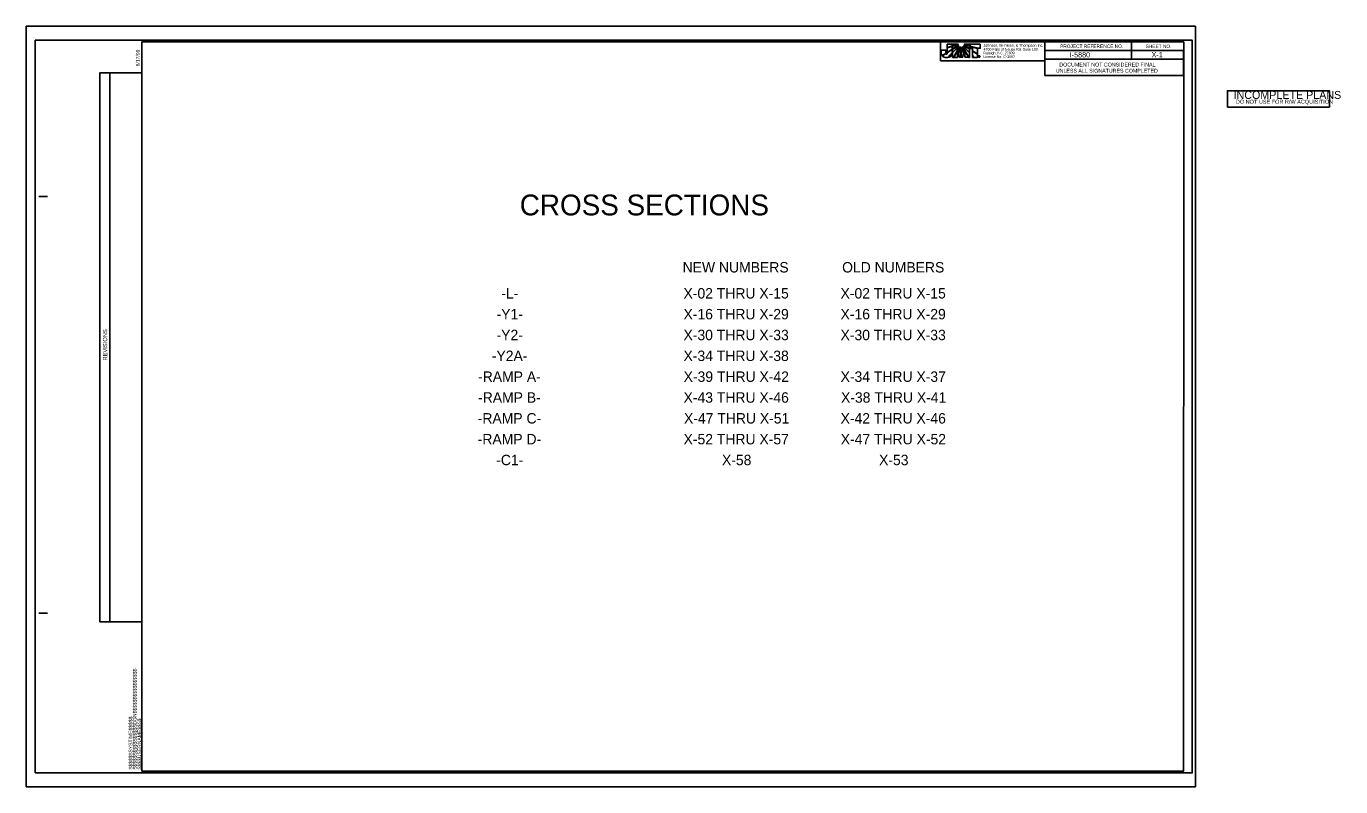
# Model space of a CAD drawing. Extents: x 2862872 to 2864765, y 971793 to 972888.
import ezdxf

# ---------------------------------------------------------------- set-up
doc = ezdxf.new("R2010")
doc.units = 0
for name, color, linetype in [('Prop Dimension Text', 7, 'Continuous'), ('Scratch_Level_0', 7, 'Continuous'), ('Sheet Block Revision CELL', 7, 'Continuous'), ('Sheet Cutting Line CELL', 7, 'Continuous'), ('Sheet Data Field CELL', 7, 'Continuous'), ('Sheet Plan CELL', 7, 'Continuous'), ('Sheet Plot Border Inside CELL', 7, 'Continuous'), ('Sheet Plot Border Outside CELL', 7, 'Continuous'), ('Sheet Sticker Exception Certification CELL', 7, 'Continuous'), ('Sheet Sticker Incomplete CELL', 7, 'Continuous'), ('Sheet XS Number', 7, 'Continuous')]:
    doc.layers.add(name, color=color, linetype=linetype)

msp = doc.modelspace()

# ---------------------------------------------------------------- linework, layer by layer
at = {"layer": 'Prop Dimension Text'}
for p, q in [((2864205.2, 972862.5), (2864198.2, 972862.5)), ((2864198.2, 972862.5), (2864198.2, 972857.9)), ((2864198.2, 972857.9), (2864205.2, 972859.8)), ((2864205.2, 972859.3), (2864198.2, 972857.3)), ((2864198.2, 972857.3), (2864198.2, 972850.8)), ((2864198.2, 972850.8), (2864205.2, 972855.2)), ((2864205.2, 972859.8), (2864205.2, 972862.5)), ((2864205.2, 972855.2), (2864205.2, 972859.3)), ((2864213.8, 972862.6), (2864205.9, 972862.6)), ((2864205.9, 972862.6), (2864205.9, 972860.1)), ((2864205.9, 972860.1), (2864211.8, 972861.7)), ((2864211.8, 972861.1), (2864205.9, 972859.5)), ((2864205.9, 972859.5), (2864205.9, 972855.7)), ((2864205.9, 972855.7), (2864211.2, 972859.1)), ((2864212, 972859), (2864205.9, 972855.1)), ((2864205.9, 972850.7), (2864213.3, 972858.4)), ((2864213.6, 972858), (2864205.9, 972850)), ((2864205.9, 972855.1), (2864205.9, 972850.7)), ((2864205.9, 972850), (2864205.9, 972843.6)), ((2864207.1, 972843.6), (2864212.8, 972854)), ((2864212.8, 972853), (2864207.6, 972843.6)), ((2864211.2, 972859.1), (2864214.1, 972861.4)), ((2864211.8, 972861.7), (2864213.8, 972862.6)), ((2864214.1, 972861.4), (2864211.8, 972861.1)), ((2864214.7, 972860.3), (2864212, 972859)), ((2864212.8, 972854), (2864212.8, 972855.8)), ((2864212.8, 972855.8), (2864213.1, 972854.6)), ((2864212.9, 972843.6), (2864212.8, 972853)), ((2864213.1, 972854.6), (2864214.6, 972857.2)), ((2864213.3, 972858.4), (2864214.7, 972860.3)), ((2864215.1, 972857.1), (2864213.3, 972853.9)), ((2864213.3, 972853.9), (2864214.5, 972849.7)), ((2864215.5, 972859.5), (2864213.6, 972858)), ((2864214.5, 972849.7), (2864216.3, 972856.7)), ((2864214.6, 972857.2), (2864215.5, 972859.5)), ((2864216.7, 972856.3), (2864214.7, 972848.7)), ((2864216.5, 972858.9), (2864215.1, 972857.1)), ((2864216.3, 972856.7), (2864216.5, 972858.9)), ((2864217.6, 972858.5), (2864216.7, 972856.3)), ((2864217.9, 972853), (2864217.6, 972858.5)), ((2864218, 972843.7), (2864217.9, 972853)), ((2864218.8, 972858.5), (2864218.4, 972853)), ((2864218.4, 972853), (2864218.5, 972843.7)), ((2864219.7, 972856.3), (2864218.8, 972858.5)), ((2864221.7, 972848.6), (2864219.7, 972856.3)), ((2864219.9, 972858.9), (2864220.2, 972856.6)), ((2864221.3, 972857.1), (2864219.9, 972858.9)), ((2864220.2, 972856.6), (2864222, 972849.5)), ((2864220.9, 972859.5), (2864221.8, 972857.2)), ((2864222.8, 972858.1), (2864220.9, 972859.5)), ((2864223.1, 972853.8), (2864221.3, 972857.1)), ((2864221.7, 972860.3), (2864223.1, 972858.4)), ((2864224.4, 972859), (2864221.7, 972860.3)), ((2864221.8, 972857.2), (2864223.3, 972854.5)), ((2864222, 972849.5), (2864223.1, 972853.8)), ((2864222.3, 972861.4), (2864225.3, 972859)), ((2864224.5, 972861.1), (2864222.3, 972861.4)), ((2864230.5, 972862.6), (2864222.7, 972862.6)), ((2864222.7, 972862.6), (2864224.7, 972861.7)), ((2864230.5, 972849.9), (2864222.8, 972858.1)), ((2864223.1, 972858.4), (2864230.5, 972850.7)), ((2864223.3, 972854.5), (2864223.6, 972855.8)), ((2864223.6, 972855.8), (2864223.6, 972853.8)), ((2864223.6, 972853.8), (2864229.3, 972843.6)), ((2864228.7, 972843.7), (2864223.6, 972852.8)), ((2864223.6, 972852.8), (2864223.6, 972843.7)), ((2864230.5, 972855.2), (2864224.4, 972859)), ((2864230.5, 972859.5), (2864224.5, 972861.1)), ((2864224.7, 972861.7), (2864230.5, 972860)), ((2864225.3, 972859), (2864230.5, 972855.8)), ((2864230.5, 972860), (2864230.5, 972862.6)), ((2864230.5, 972855.8), (2864230.5, 972859.5)), ((2864230.5, 972850.7), (2864230.5, 972855.2)), ((2864230.5, 972843.6), (2864230.5, 972849.9)), ((2864245.8, 972862.6), (2864231.1, 972862.6)), ((2864231.1, 972862.6), (2864231.1, 972859.9)), ((2864231.1, 972859.9), (2864231.1, 972859.8)), ((2864231.1, 972859.8), (2864242.7, 972856.6)), ((2864231.1, 972859.4), (2864231.1, 972859.3)), ((2864241.9, 972856.3), (2864231.1, 972859.4)), ((2864231.1, 972859.3), (2864231.1, 972856.5)), ((2864231.1, 972856.5), (2864234.7, 972856.5)), ((2864234.7, 972856.5), (2864234.7, 972853.1)), ((2864234.7, 972853.1), (2864241.9, 972848.5)), ((2864234.7, 972852.6), (2864234.7, 972846.3)), ((2864241.9, 972848), (2864234.7, 972852.6)), ((2864241.9, 972848.5), (2864241.9, 972856.3)), ((2864242.7, 972856.6), (2864245.8, 972856.6)), ((2864245.8, 972856.6), (2864245.8, 972862.6)), ((2864205.9, 972843.6), (2864207.1, 972843.6)), ((2864207.6, 972843.6), (2864212.9, 972843.6)), ((2864214.7, 972848.7), (2864216, 972843.7)), ((2864216, 972843.7), (2864218, 972843.7)), ((2864218.5, 972843.7), (2864220.4, 972843.7)), ((2864220.4, 972843.7), (2864221.7, 972848.6)), ((2864223.6, 972843.7), (2864228.7, 972843.7)), ((2864229.3, 972843.6), (2864230.5, 972843.6)), ((2864234.7, 972846.3), (2864237.2, 972843.6)), ((2864236.5, 972843.6), (2864234.7, 972845.6)), ((2864234.7, 972845.6), (2864234.7, 972843.6)), ((2864234.7, 972843.6), (2864236.5, 972843.6)), ((2864237.2, 972843.6), (2864242, 972843.6)), ((2864242, 972843.6), (2864241.9, 972848)), ((2864243.8, 972844.3), (2864243.8, 972845.4)), ((2864243.8, 972845.4), (2864244.2, 972845.4)), ((2864244, 972844.3), (2864243.8, 972844.3)), ((2864244.2, 972845.2), (2864244, 972845.2)), ((2864244, 972845.2), (2864244, 972844.9)), ((2864244, 972844.9), (2864244.2, 972844.9)), ((2864244.2, 972844.7), (2864244, 972844.7)), ((2864244, 972844.7), (2864244, 972844.3)), ((2864244.2, 972846), (2864244.2, 972845.8)), ((2864244.2, 972845.8), (2864244.2, 972846)), ((2864244.2, 972845.4), (2864244.2, 972845.2)), ((2864244.2, 972845.2), (2864244.2, 972845.4)), ((2864244.2, 972845.4), (2864244.3, 972845.4)), ((2864244.3, 972845.2), (2864244.2, 972845.2)), ((2864244.2, 972844.9), (2864244.2, 972844.7)), ((2864244.2, 972844.7), (2864244.2, 972844.9)), ((2864244.2, 972844.9), (2864244.2, 972844.9)), ((2864244.2, 972844.7), (2864244.2, 972844.7)), ((2864244.2, 972843.9), (2864244.2, 972843.7)), ((2864244.2, 972843.7), (2864244.2, 972843.9)), ((2864244.2, 972843.9), (2864244.2, 972843.9)), ((2864244.2, 972843.7), (2864244.2, 972843.7))]:
    msp.add_line(p, q, dxfattribs=at)
msp.add_lwpolyline([(2864188.7, 972838.8), (2864338.6, 972838.8), (2864338.6, 972865.8), (2864188.7, 972865.8)], close=True, dxfattribs=at)
for points in [[(2864198.2, 972857.9), (2864205.2, 972859.8), (2864205.2, 972862.5), (2864198.2, 972862.5), (2864198.2, 972857.9)], [(2864198.2, 972850.8), (2864205.2, 972855.2), (2864205.2, 972859.3), (2864198.2, 972857.3), (2864198.2, 972850.8)], [(2864211.8, 972861.7), (2864213.8, 972862.6), (2864205.9, 972862.6), (2864205.9, 972860.1), (2864211.8, 972861.7)], [(2864205.9, 972859.5), (2864205.9, 972855.7), (2864211.2, 972859.1), (2864214.1, 972861.4), (2864211.8, 972861.1), (2864205.9, 972859.5)], [(2864205.9, 972855.1), (2864205.9, 972850.7), (2864213.3, 972858.4), (2864214.7, 972860.3), (2864212, 972859), (2864205.9, 972855.1)], [(2864215.5, 972859.5), (2864213.6, 972858), (2864205.9, 972850), (2864205.9, 972843.6), (2864207.1, 972843.6), (2864212.8, 972854), (2864212.8, 972855.8), (2864213.1, 972854.6), (2864214.6, 972857.2), (2864215.5, 972859.5)], [(2864207.6, 972843.6), (2864212.9, 972843.6), (2864212.8, 972853), (2864207.6, 972843.6)], [(2864216.5, 972858.9), (2864215.1, 972857.1), (2864213.3, 972853.9), (2864214.5, 972849.7), (2864216.3, 972856.7), (2864216.5, 972858.9)], [(2864216.7, 972856.3), (2864214.7, 972848.7), (2864216, 972843.7), (2864218, 972843.7), (2864217.9, 972853), (2864217.6, 972858.5), (2864216.7, 972856.3)], [(2864218.8, 972858.5), (2864218.4, 972853), (2864218.5, 972843.7), (2864220.4, 972843.7), (2864221.7, 972848.6), (2864219.7, 972856.3), (2864218.8, 972858.5)], [(2864219.9, 972858.9), (2864220.2, 972856.6), (2864222, 972849.5), (2864223.1, 972853.8), (2864221.3, 972857.1), (2864219.9, 972858.9)], [(2864220.9, 972859.5), (2864221.8, 972857.2), (2864223.3, 972854.5), (2864223.6, 972855.8), (2864223.6, 972853.8), (2864229.3, 972843.6), (2864230.5, 972843.6), (2864230.5, 972849.9), (2864222.8, 972858.1), (2864220.9, 972859.5)], [(2864221.7, 972860.3), (2864223.1, 972858.4), (2864230.5, 972850.7), (2864230.5, 972855.2), (2864224.4, 972859), (2864221.7, 972860.3)], [(2864222.3, 972861.4), (2864225.3, 972859), (2864230.5, 972855.8), (2864230.5, 972859.5), (2864224.5, 972861.1), (2864222.3, 972861.4)], [(2864224.7, 972861.7), (2864230.5, 972860), (2864230.5, 972862.6), (2864222.7, 972862.6), (2864224.7, 972861.7)], [(2864223.6, 972843.7), (2864228.7, 972843.7), (2864223.6, 972852.8), (2864223.6, 972843.7)], [(2864245.8, 972862.6), (2864231.1, 972862.6), (2864231.1, 972859.9), (2864231.1, 972859.8), (2864242.7, 972856.6), (2864245.8, 972856.6), (2864245.8, 972862.6)], [(2864231.1, 972859.4), (2864231.1, 972859.3), (2864231.1, 972856.5), (2864234.7, 972856.5), (2864234.7, 972853.1), (2864241.9, 972848.5), (2864241.9, 972856.3), (2864231.1, 972859.4)], [(2864234.7, 972852.6), (2864234.7, 972846.3), (2864237.2, 972843.6), (2864242, 972843.6), (2864241.9, 972848), (2864234.7, 972852.6), (2864234.7, 972852.6)], [(2864234.7, 972843.6), (2864234.7, 972843.6), (2864236.5, 972843.6), (2864234.7, 972845.6), (2864234.7, 972843.6)], [(2864244.7, 972844.6), (2864244.7, 972844.5), (2864244.7, 972844.5), (2864244.7, 972844.4), (2864244.7, 972844.3), (2864244.5, 972844.3)]]:
    msp.add_lwpolyline(points, dxfattribs=at)
for points, degree in [([(2864196.2, 972853.8), (2864196.2, 972853.8), (2864189.7, 972853.8), (2864189.7, 972853.8), (2864189.7, 972853.8), (2864189.7, 972849.7), (2864189.7, 972849.7), (2864189.7, 972849.7), (2864189.7, 972849.3), (2864189.7, 972849.3), (2864189.7, 972848), (2864190.1, 972847), (2864190.8, 972846.2), (2864190.8, 972846.2), (2864196.2, 972849.4), (2864196.2, 972849.5), (2864196.2, 972849.5), (2864196.2, 972853.8), (2864196.2, 972853.8)], 3), ([(2864197.2, 972848), (2864196.8, 972848), (2864196.4, 972848.2), (2864196.2, 972849), (2864196.2, 972849), (2864191.2, 972845.8), (2864191.2, 972845.8), (2864192.8, 972844.2), (2864195.2, 972843.2), (2864197.3, 972843.2), (2864197.9, 972843.2), (2864198.3, 972843.3), (2864198.9, 972843.4), (2864198.9, 972843.4), (2864205.2, 972849.9), (2864205.2, 972849.9), (2864205.2, 972849.9), (2864205.2, 972854.7), (2864205.2, 972854.7), (2864205.2, 972854.7), (2864198.2, 972850.2), (2864198.2, 972850.2), (2864198.2, 972848.4), (2864197.7, 972848), (2864197.2, 972848)], 3), ([(2864197.2, 972848), (2864196.8, 972848), (2864196.4, 972848.2), (2864196.2, 972849), (2864196.2, 972849), (2864191.2, 972845.8), (2864191.2, 972845.8), (2864192.8, 972844.2), (2864195.2, 972843.2), (2864197.3, 972843.2), (2864197.9, 972843.2), (2864198.3, 972843.3), (2864198.9, 972843.4), (2864198.9, 972843.4), (2864205.2, 972849.9), (2864205.2, 972849.9), (2864205.2, 972849.9), (2864205.2, 972854.7), (2864205.2, 972854.7), (2864205.2, 972854.7), (2864198.2, 972850.2), (2864198.2, 972850.2), (2864198.2, 972848.4), (2864197.7, 972848), (2864197.2, 972848)], 3), ([(2864205.2, 972849.2), (2864205.2, 972849.2), (2864199.7, 972843.6), (2864199.7, 972843.6), (2864202.4, 972844.2), (2864205.1, 972846), (2864205.2, 972849.2)], 3), ([(2864244.2, 972843.7), (2864243.9, 972843.7), (2864243.6, 972843.8), (2864243.4, 972844), (2864243.2, 972844.2), (2864243, 972844.5), (2864243, 972844.8), (2864243, 972845.2), (2864243.2, 972845.5), (2864243.4, 972845.7), (2864243.6, 972845.9), (2864243.9, 972846), (2864244.2, 972846)], 3), ([(2864244.2, 972845.8), (2864244, 972845.8), (2864243.7, 972845.7), (2864243.6, 972845.5), (2864243.4, 972845.3), (2864243.3, 972845.1), (2864243.3, 972844.8), (2864243.3, 972844.6), (2864243.4, 972844.4), (2864243.6, 972844.2), (2864243.7, 972844), (2864244, 972843.9), (2864244.2, 972843.9)], 3), ([(2864244.2, 972846), (2864244.6, 972846), (2864244.8, 972845.9), (2864245.1, 972845.7), (2864245.3, 972845.5), (2864245.4, 972845.2), (2864245.4, 972844.8)], 3), ([(2864244.2, 972843.9), (2864244.5, 972843.9), (2864244.7, 972844), (2864244.9, 972844.2), (2864245.1, 972844.4), (2864245.2, 972844.6), (2864245.2, 972844.8), (2864245.2, 972845.1), (2864245.1, 972845.3), (2864244.9, 972845.5), (2864244.7, 972845.7), (2864244.5, 972845.8), (2864244.2, 972845.8)], 3), ([(2864244.2, 972844.9), (2864244.4, 972844.9), (2864244.5, 972845), (2864244.5, 972845.1), (2864244.5, 972845.1), (2864244.4, 972845.2), (2864244.3, 972845.2)], 3), ([(2864245.4, 972844.8), (2864245.4, 972844.5), (2864245.3, 972844.2), (2864245.1, 972844), (2864244.9, 972843.8), (2864244.6, 972843.7), (2864244.2, 972843.7)], 3), ([(2864244.4, 972844.7), (2864244.4, 972844.7), (2864244.3, 972844.7), (2864244.2, 972844.7)], 2), ([(2864244.3, 972845.4), (2864244.6, 972845.4), (2864244.7, 972845.3), (2864244.7, 972845.1), (2864244.7, 972845), (2864244.7, 972844.9), (2864244.6, 972844.8)], 3), ([(2864244.5, 972844.3), (2864244.5, 972844.4), (2864244.5, 972844.4), (2864244.5, 972844.5), (2864244.5, 972844.6), (2864244.5, 972844.7), (2864244.4, 972844.7)], 3), ([(2864244.6, 972844.8), (2864244.7, 972844.8), (2864244.7, 972844.7), (2864244.7, 972844.6)], 2)]:
    msp.add_open_spline(points, degree=degree, dxfattribs=at)
at = {"layer": 'Sheet Block Revision CELL'}
msp.add_line((2862992.6, 972030.8), (2862992.6, 972821.5), dxfattribs=at)
msp.add_line((2862992.6, 972030.8), (2862992.6, 972821.5), dxfattribs=at)
msp.add_lwpolyline([(2862978.1, 972030.8), (2862978.1, 972821.5), (2863038.6, 972821.5), (2863038.6, 972030.8)], close=True, dxfattribs=at)
msp.add_lwpolyline([(2862978.1, 972030.8), (2862978.1, 972821.5), (2863038.6, 972821.5), (2863038.6, 972030.8)], close=True, dxfattribs=at)
at = {"layer": 'Sheet Cutting Line CELL'}
for p, q in [((2864555.6, 972888.3), (2862872.1, 972888.3)), ((2862872.1, 972888.3), (2862872.1, 971793.3)), ((2862872.1, 971793.3), (2864555.6, 971793.3))]:
    msp.add_line(p, q, dxfattribs=at)
at = {"layer": 'Sheet Plan CELL'}
for p, q in [((2863038.6, 972865.8), (2863038.6, 972865.8)), ((2863038.6, 972865.8), (2863038.6, 972865.8)), ((2864338.6, 972853.3), (2864538.6, 972853.3)), ((2864338.6, 972853.3), (2864538.6, 972853.3)), ((2864463.6, 972865.8), (2864463.6, 972840.8)), ((2864463.6, 972865.8), (2864463.6, 972840.8)), ((2864338.6, 972840.8), (2864538.6, 972840.8)), ((2864338.6, 972840.8), (2864538.6, 972840.8)), ((2864338.6, 972840.8), (2864538.6, 972840.8)), ((2864338.6, 972840.8), (2864538.6, 972840.8)), ((2862890.1, 972643.3), (2862902.6, 972643.3)), ((2862890.1, 972643.3), (2862902.6, 972643.3)), ((2862890.1, 972043.3), (2862902.6, 972043.3)), ((2862890.1, 972043.3), (2862902.6, 972043.3)), ((2863038.6, 971815.8), (2863038.6, 971815.8)), ((2863038.6, 971815.8), (2863038.6, 971815.8))]:
    msp.add_line(p, q, dxfattribs=at)
for points in [[(2864538.7, 972865.8), (2863038.6, 972865.8), (2863038.6, 971815.8), (2864538.6, 971815.8)], [(2864538.7, 972865.8), (2863038.6, 972865.8), (2863038.6, 971815.8), (2864538.6, 971815.8)], [(2864338.6, 972865.8), (2864538.7, 972865.8), (2864538.6, 972840.8), (2864338.6, 972840.8)], [(2864338.6, 972865.8), (2864538.7, 972865.8), (2864538.6, 972840.8), (2864338.6, 972840.8)]]:
    msp.add_lwpolyline(points, close=True, dxfattribs=at)
at = {"layer": 'Sheet Plot Border Inside CELL'}
msp.add_lwpolyline([(2862885.1, 971813.3), (2864551.1, 971813.3), (2864551.1, 972868.3), (2862885.1, 972868.3)], close=True, dxfattribs=at)
at = {"layer": 'Sheet Plot Border Outside CELL'}
msp.add_lwpolyline([(2862872.1, 971793.3), (2864555.6, 971793.3), (2864555.6, 972888.3), (2862872.1, 972888.3)], close=True, dxfattribs=at)
msp.add_lwpolyline([(2862872.1, 971793.3), (2864555.6, 971793.3), (2864555.6, 972888.3), (2862872.1, 972888.3)], close=True, dxfattribs=at)
at = {"layer": 'Sheet Sticker Exception Certification CELL'}
for p, q in [((2864338.6, 972817.3), (2864338.6, 972840.8)), ((2864338.6, 972840.8), (2864538.6, 972840.8)), ((2864338.6, 972817.3), (2864338.6, 972840.8)), ((2864338.6, 972840.8), (2864538.6, 972840.8)), ((2864338.6, 972817.3), (2864338.6, 972840.8)), ((2864338.6, 972840.8), (2864538.6, 972840.8)), ((2864338.6, 972817.3), (2864338.6, 972840.8)), ((2864338.6, 972840.8), (2864538.6, 972840.8)), ((2864538.6, 972840.8), (2864538.6, 972817.3)), ((2864538.6, 972840.8), (2864538.6, 972817.3)), ((2864538.6, 972840.8), (2864538.6, 972817.3)), ((2864538.6, 972840.8), (2864538.6, 972817.3)), ((2864538.6, 972817.3), (2864338.6, 972817.3)), ((2864538.6, 972817.3), (2864338.6, 972817.3)), ((2864538.6, 972817.3), (2864338.6, 972817.3)), ((2864538.6, 972817.3), (2864338.6, 972817.3))]:
    msp.add_line(p, q, dxfattribs=at)
at = {"layer": 'Sheet Sticker Incomplete CELL'}
msp.add_lwpolyline([(2864601.6, 972772), (2864601.6, 972795.5), (2864748.6, 972795.5), (2864748.6, 972772)], close=True, dxfattribs=at)

# ---------------------------------------------------------------- texts
at = {"layer": 'Prop Dimension Text'}
for s, height, p in [('Johnson, Mirmiran, & Thompson Inc.', 3.83, (2864250.4, 972858.9)), ('4700 Falls of Neuse Rd, Suite 100, ', 3.721, (2864250.4, 972853.3)), ('Raleigh, NC, 27609', 3.721, (2864250.4, 972848)), ('License No: C-3097', 3.721, (2864250.4, 972842.7))]:
    msp.add_text(s, height=height, rotation=360, dxfattribs=at).set_placement(p)
at = {"layer": 'Scratch_Level_0'}
for s, p in [('NEW NUMBERS', (2863817.2, 972533.8)), ('OLD NUMBERS', (2864046.9, 972533.8)), ('X-02 THRU X-15', (2864044.6, 972496.3)), ('X-16 THRU X-29', (2864044.6, 972466.3)), ('X-30 THRU X-33', (2864044.6, 972436.3)), ('X-34 THRU X-37', (2864044.7, 972376.3)), ('X-38 THRU X-41', (2864045.3, 972346.3)), ('X-42 THRU X-46', (2864044.7, 972316.3)), ('X-47 THRU X-52', (2864044.9, 972286.3)), ('X-53', (2864100.1, 972256.3))]:
    msp.add_text(s, height=15, dxfattribs=at).set_placement(p)
at = {"layer": 'Sheet Block Revision CELL'}
msp.add_text('REVISIONS', height=6, rotation=90, dxfattribs=at).set_placement((2862988.6, 972407))
msp.add_text('REVISIONS', height=6, rotation=90, dxfattribs=at).set_placement((2862988.6, 972407))
at = {"layer": 'Sheet Data Field CELL'}
for s, p in [('I-5880   ', (2864374.6, 972843.5)), ('X-1', (2864492.5, 972843.6))]:
    msp.add_text(s, height=7.5, rotation=0, dxfattribs=at).set_placement(p)
at = {"layer": 'Sheet Plan CELL'}
for s, height, rotation, p in [('8/17/99', 5.25, 90, (2863035.4, 972830.6)), ('8/17/99', 5.25, 90, (2863035.4, 972830.6)), ('PROJECT REFERENCE NO.', 5, 0, (2864360.8, 972857.1)), ('PROJECT REFERENCE NO.', 5, 0, (2864360.8, 972857.1)), ('SHEET NO.', 5, 0, (2864483.9, 972857)), ('SHEET NO.', 5, 0, (2864483.9, 972857)), ('$$$$$$$$$$$$$$$$DGN$$$$$$$$$$$$$$$$', 5.25, 90, (2863031, 971818.2)), ('$$$$$$$$$$$$$$$$DGN$$$$$$$$$$$$$$$$', 5.25, 90, (2863031, 971818.2)), ('$$$$$$SYSTIME$$$$$', 5.25, 90, (2863024.9, 971818.2)), ('$$$$$$SYSTIME$$$$$', 5.25, 90, (2863024.9, 971818.2)), ('$$$$USERNAME$$$$', 5.25, 90, (2863037.5, 971818.2)), ('$$$$USERNAME$$$$', 5.25, 90, (2863037.5, 971818.2))]:
    msp.add_text(s, height=height, rotation=rotation, dxfattribs=at).set_placement(p)
at = {"layer": 'Sheet Sticker Exception Certification CELL'}
for s, p in [('DOCUMENT NOT CONSIDERED FINAL', (2864359.7, 972830.4)), ('DOCUMENT NOT CONSIDERED FINAL', (2864359.7, 972830.4)), ('DOCUMENT NOT CONSIDERED FINAL', (2864359.7, 972830.4)), ('DOCUMENT NOT CONSIDERED FINAL', (2864359.7, 972830.4)), ('UNLESS ALL SIGNATURES COMPLETED', (2864354.6, 972821.6)), ('UNLESS ALL SIGNATURES COMPLETED', (2864354.6, 972821.6)), ('UNLESS ALL SIGNATURES COMPLETED', (2864354.6, 972821.6)), ('UNLESS ALL SIGNATURES COMPLETED', (2864354.6, 972821.6))]:
    msp.add_text(s, height=5.5, dxfattribs=at).set_placement(p)
at = {"layer": 'Sheet Sticker Incomplete CELL'}
for s, height, p in [('INCOMPLETE PLANS', 11.52, (2864610.6, 972783.7)), ('DO NOT USE FOR R/W ACQUISITION', 5.76, (2864613.8, 972776.8))]:
    msp.add_text(s, height=height, dxfattribs=at).set_placement(p)
at = {"layer": 'Sheet XS Number'}
for s, height, p in [('CROSS SECTIONS', 30, (2863582.7, 972616)), ('-L-', 15, (2863556.1, 972496.3)), ('X-02 THRU X-15', 15, (2863818.5, 972496.3)), ('-Y1-', 15, (2863549.3, 972466.3)), ('X-16 THRU X-29', 15, (2863818.5, 972466.3)), ('-Y2-', 15, (2863549.3, 972436.3)), ('X-30 THRU X-33', 15, (2863818.5, 972436.3)), ('-Y2A-', 15, (2863542.5, 972406.3)), ('X-34 THRU X-38', 15, (2863818.5, 972406.3)), ('-RAMP A-', 15, (2863522.7, 972376.3)), ('X-39 THRU X-42', 15, (2863818.7, 972376.3)), ('-RAMP B-', 15, (2863522.7, 972346.3)), ('X-43 THRU X-46', 15, (2863818.6, 972346.3)), ('-RAMP C-', 15, (2863522.2, 972316.3)), ('X-47 THRU X-51', 15, (2863819.2, 972316.3)), ('-RAMP D-', 15, (2863522.2, 972286.3)), ('X-52 THRU X-57', 15, (2863818.6, 972286.3)), ('-C1-', 15, (2863548.8, 972256.3)), ('X-58', 15, (2863873.9, 972256.3))]:
    msp.add_text(s, height=height, dxfattribs=at).set_placement(p)

doc.saveas('drawing.dxf')
